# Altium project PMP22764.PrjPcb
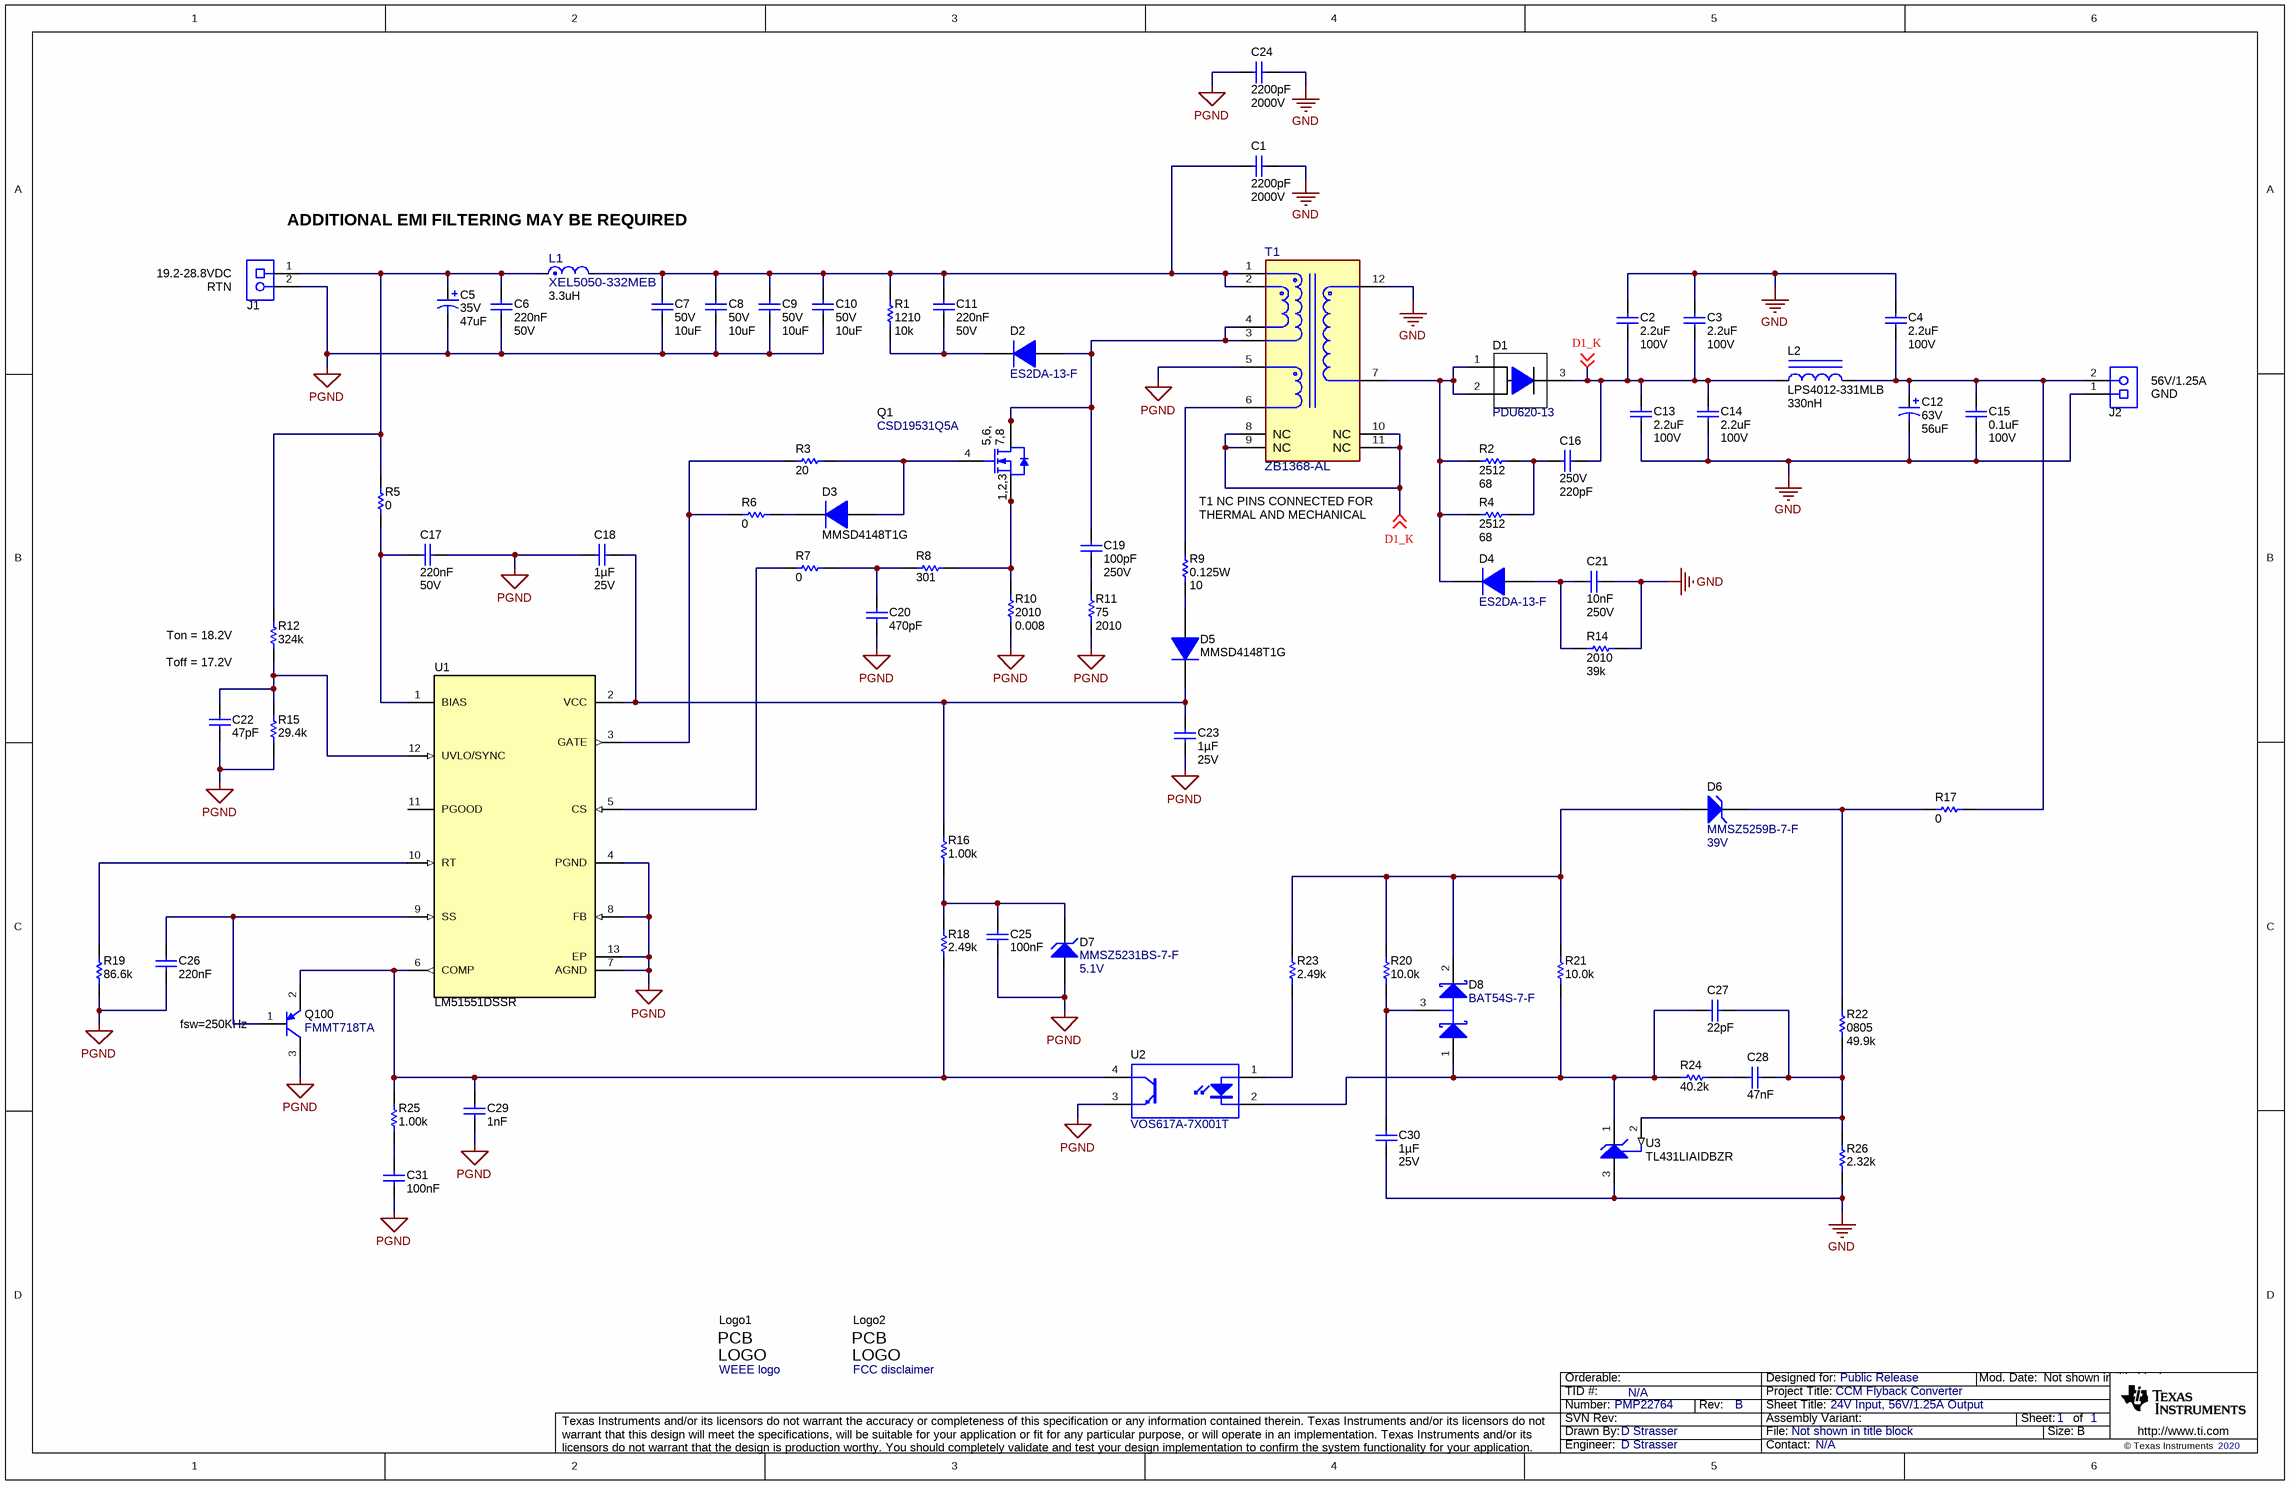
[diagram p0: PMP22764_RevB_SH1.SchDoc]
CopyrightYear: 2020; PCB_Layout: D Strasser; PCB_Rev: B; PRJ_Customer: Public Release; PRJ_Engineer: D Strasser; PRJ_Number: PMP22764; PRJ_Title: CCM Flyback Converter; SCH_Rev: B; TechSupport: N/A; TID: N/A
1 sheet, 76 parts. Net scope: global (net labels, ports and power ports of the same name join across sheets).
Board file: PMP22764_RevB.PcbDoc

## Sheet PMP22764_RevB_SH1.SchDoc: 24V Input, 56V/1.25A Output
size 431 x 279 mm; Date: Not shown in title block; ApprovedBy: Not shown in title block; CheckedBy: Not shown in title block; Author: Not shown in title block; CompanyName: Not shown in title block; DrawnBy: D Strasser; Engineer: Not shown in title block; Organization: Not shown in title block; Address1: Not shown in title block; Address2: Not shown in title block; Address3: Not shown in title block; Address4: Not shown in title block; DocumentNumber: 1; Revision: Use project parameter SCH_Rev; SheetNumber: 1; SheetTotal: 1; PageSetup: Record=PageOptions¦CenterHorizontal=True¦CenterVertical=True¦PrintScale=1.00¦XCorrection=1.00¦YCorrection=1.00¦PrintKind=0¦BorderSize=5000000¦LeftOffset=0¦BottomOffset=0¦Orientation=2¦PaperLength=1000¦PaperWidth=1000¦Scale=100¦PaperSource=15¦PrintQuality=600¦MediaType=1¦DitherType=10¦PaperKind=Letter¦PrintScaleMode=1

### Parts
C1  ValueDisplayed: 2200pF  Value2: 2000V  [1812_HV]  (hidden comment: Capacitor)
C2  ValueDisplayed: 2.2uF  Value2: 100V  [1210_270]  (hidden comment: Capacitor)
C3  ValueDisplayed: 2.2uF  Value2: 100V  [1210_270]  (hidden comment: Capacitor)
C4  ValueDisplayed: 2.2uF  Value2: 100V  [1210_270]  (hidden comment: Capacitor)
C5  VDC_V: 35V  ValueDisplayed: 47uF  [SM_RADIAL_6.3AMM]  (hidden comment: EEHZC1V470P)
C6  Cap_F: 220nF  VDC_V: 50V  [0805_HV]  (hidden comment: UMK212B7224KG-T)
C7  VDC_V: 50V  ValueDisplayed: 10uF  [1210_280]  (hidden comment: UMK325AB7106KM-T)
C8  VDC_V: 50V  ValueDisplayed: 10uF  [1210_280]  (hidden comment: UMK325AB7106KM-T)
C9  VDC_V: 50V  ValueDisplayed: 10uF  [1210_280]  (hidden comment: UMK325AB7106KM-T)
C10  VDC_V: 50V  ValueDisplayed: 10uF  [1210_280]  (hidden comment: UMK325AB7106KM-T)
C11  Cap_F: 220nF  VDC_V: 50V  [0805_HV]  (hidden comment: UMK212B7224KG-T)
C12  VDC_V: 63V  ValueDisplayed: 56uF  [SM_RADIAL_10BMM]  (hidden comment: EEHZC1J560P)
C13  ValueDisplayed: 2.2uF  Value2: 100V  [1210_270]  (hidden comment: Capacitor)
C14  ValueDisplayed: 2.2uF  Value2: 100V  [1210_270]  (hidden comment: Capacitor)
C15  ValueDisplayed: 0.1uF  Value2: 100V  [0805_HV]  (hidden comment: Capacitor)
C16  VDC_V: 250V  ValueDisplayed: 220pF  [0603]  (hidden comment: C1608C0G2E221J080AA)
C17  Cap_F: 220nF  VDC_V: 50V  [0805_HV]  (hidden comment: UMK212B7224KG-T)
C18  Cap_F: 1µF  VDC_V: 25V  [0805_HV]  (hidden comment: TMK212B7105KG-T)
C19  ValueDisplayed: 100pF  Value2: 250V  [0805_HV]  (hidden comment: Capacitor)
C20  Cap_F: 470pF  [0603L]  (hidden comment: 885012206081)
C21  Cap_F: 10nF  VDC_V: 250V  [0805_HV]  (hidden comment: QMK212B7103KG-T)
C22  ValueDisplayed: 47pF  [0603L]  (hidden comment: GRM1885C1H470JA01D)
C23  Cap_F: 1µF  VDC_V: 25V  [0805_HV]  (hidden comment: TMK212B7105KG-T)
C24  ValueDisplayed: 2200pF  Value2: 2000V  [1812_HV]  (hidden comment: Capacitor)
C25  Cap_F: 100nF  [0603L]  (hidden comment: 885012206071)
C26  Cap_F: 220nF  [0603L]  (hidden comment: C1608X7R1E224K080AC)
C27  ValueDisplayed: 22pF  [0603L]  (hidden comment: C0603C220J5GACTU)
C28  Cap_F: 47nF  [0603L]  (hidden comment: GRM188R71E473KA01D)
C29  Cap_F: 1nF  [0603L]  (hidden comment: 885012206083)
C30  Cap_F: 1µF  VDC_V: 25V  [0805_HV]  (hidden comment: TMK212B7105KG-T)
C31  Cap_F: 100nF  [0603L]  (hidden comment: 885012206071)
D1  PDU620-13  [POWERDI5]
D2  ES2DA-13-F  [SMA]
D3  MMSD4148T1G  [SOD-123]
D4  ES2DA-13-F  [SMA]
D5  MMSD4148T1G  [SOD-123]
D6  MMSZ5259B-7-F  value 39V  [SOD-123]
D7  MMSZ5231BS-7-F  value 5.1V  [SOD-323]
D8  BAT54S-7-F  [SOT-23]
J1  ED555/2DS  [TERM_BLK_ED555-2DS]  (value not drawn)
J2  Receptacle_2x1  [TERM_BLK_ED555-2DS]  (value not drawn)
L1  XEL5050-332MEB  value 3.3uH  [FP-XEL5050-332MEB_SMT_IND_5MM48_5MM28-MFG]
L2  ValueDisplayed: 330nH  [LPS4012]  (hidden comment: LPS4012-331MLB)
Logo1  WEEE logo  [WEEE_Minimum]  (no BOM)
Logo2  FCC disclaimer  [FCC_disclaimer]  (no BOM)
Q1  CSD19531Q5A  [DQJ0008A]
Q100  FMMT718TA  [SOT-23L]
R1  PackageReference: 1210  ValueDisplayed: 10k  [1210L]  (hidden comment: RC1210JR-0710KL)
R2  ValueDisplayed: 68  [2512]  (hidden comment: CRCW251268R0JNEG)
R3  ValueDisplayed: 20  [0603L]  (hidden comment: CRCW060320R0JNEA)
R4  ValueDisplayed: 68  [2512]  (hidden comment: CRCW251268R0JNEG)
R5  ValueDisplayed: 0  [0603L]  (hidden comment: Resistor)
R6  ValueDisplayed: 0  [0603L]  (hidden comment: Resistor)
R7  ValueDisplayed: 0  [0603L]  (hidden comment: Resistor)
R8  ValueDisplayed: 301  [0603L]  (hidden comment: CRCW0603301RFKEA)
R9  Value2: 0.125W  ValueDisplayed: 10  [0805_HV]  (hidden comment: CRCW080510R0JNEA)
R10  ValueDisplayed: 0.008  [2010]  (hidden comment: PMR50HZPFU8L00)
R11  ValueDisplayed: 75  PackageReference: 2010  [2010L]  (hidden comment: Resistor)
R12  ValueDisplayed: 324k  [0603L]  (hidden comment: CRCW0603324KFKEA)
R14  ValueDisplayed: 39k  [2010]  (hidden comment: CRCW201039K0JNEF)
R15  ValueDisplayed: 29.4k  [0603L]  (hidden comment: CRCW060329K4FKEA)
R16  ValueDisplayed: 1.00k  [0603L]  (hidden comment: CRCW06031K00FKEA)
R17  ValueDisplayed: 0  [0603L]  (hidden comment: Resistor)
R18  ValueDisplayed: 2.49k  [0603L]  (hidden comment: CRCW06032K49FKEA)
R19  ValueDisplayed: 86.6k  [0603L]  (hidden comment: CRCW060386K6FKEA)
R20  ValueDisplayed: 10.0k  [0603L]  (hidden comment: CRCW060310K0FKEA)
R21  ValueDisplayed: 10.0k  [0603L]  (hidden comment: CRCW060310K0FKEA)
R22  PackageReference: 0805  ValueDisplayed: 49.9k  [0805_HV]  (hidden comment: CRCW080549K9FKEA)
R23  ValueDisplayed: 2.49k  [0603L]  (hidden comment: CRCW06032K49FKEA)
R24  ValueDisplayed: 40.2k  [0603L]  (hidden comment: CRCW060340K2FKEA)
R25  ValueDisplayed: 1.00k  [0603L]  (hidden comment: CRCW06031K00FKEA)
R26  ValueDisplayed: 2.32k  [0603L]  (hidden comment: CRCW06032K32FKEA)
T1  ZB1368-AL  [FP-ZB1368-AL_PTH_XFRMR_33MM02_26MM75-MFG]
U1  LM51551DSSR  [DSS0012B]
U2  VOS617A-7X001T  [SSOP-4_VISHAY]
U3  TL431LIAIDBZR  [DBZ0003A_N]

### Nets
GND: C1.1 C2.1 C3.1 C4.1 C12.2(-) C13.2 C14.2 C15.1 C21.2 C24.1 C30.1 J2.1 R14.2 R26.2 T1.12 U3.3(ANODE)
PGND: C5.2(-) C6.2 C7.2 C8.2 C9.2 C10.2 C17.1 C18.2 C20.1 C22.1 C23.1 C24.2 C25.2 C26.2 C29.1 C31.2 D7.2(A) J1.2 Q100.3(C) R10.2 R11.1 R15.2 R19.2 T1.5 U1.4(PGND) U1.7(AGND) U1.8(FB) U1.13(EP) U2.3(E)
D1_K: C2.2 C3.2 C13.1 C14.1 C16.1 D1.3(K) L2.1 T1.8(NC) T1.9(NC) T1.10(NC) T1.11(NC) ; off-sheet D1_K
NetC1_2: C1.2 C7.1 C8.1 C9.1 C10.1 C11.1 L1.2 R1.1 T1.1 T1.2
NetC4_2: C4.2 C12.1(+) C15.2 J2.2 L2.2 R17.1
NetC5_1: C5.1(+) C6.1 J1.1 L1.1 R5.2 R12.1
NetC11_2: C11.2 D2.1(K) R1.2
NetC16_2: C16.2 R2.2 R4.2
NetC17_2: C17.2 R5.1 U1.1(BIAS)
NetC18_1: C18.1 C23.2 D5.1(K) R16.2 U1.2(VCC)
NetC19_1: C19.1 D2.2(A) Q1.5(D) Q1.6(D) Q1.7(D) Q1.8(D) Q1.9(D) T1.3 T1.4
NetC19_2: C19.2 R11.2
NetC20_2: C20.2 R7.2 R8.1
NetC21_1: C21.1 D4.2(A) R14.1
NetC22_2: C22.2 R12.2 R15.1 U1.12(UVLO/SYNC)
NetC25_1: C25.1 D7.1(K) R16.1 R18.1
NetC26_1: C26.1 Q100.1(B) U1.9(SS)
NetC27_1: C27.1 C28.1 R22.2 R26.1 U3.2(REF)
NetC27_2: C27.2 D8.1(A) R21.2 R24.1 U2.2(K) U3.1(CATHODE)
NetC28_2: C28.2 R24.2
NetC29_2: C29.2 Q100.2(E) R18.2 R25.2 U1.6(COMP) U2.4(C)
NetC30_2: C30.2 D8.3(C) R20.2
NetC31_1: C31.1 R25.1
NetD1_1: D1.1(A) D1.2(A) D4.1(K) R2.1 R4.1 T1.7
NetD3_1: D3.1(K) R6.2
NetD3_2: D3.2(A) Q1.4(G) R3.2
NetD5_2: D5.2(A) R9.2
NetD6_1: D6.1(K) R17.2 R22.1
NetD6_2: D6.2(A) D8.2(K) R20.1 R21.1 R23.1
NetQ1_1: Q1.1(S) Q1.2(S) Q1.3(S) R8.2 R10.1
NetR3_1: R3.1 R6.1 U1.3(GATE)
NetR7_1: R7.1 U1.5(CS)
NetR9_1: R9.1 T1.6
NetR19_1: R19.1 U1.10(RT)
NetR23_2: R23.2 U2.1(A)

Not connected (* = marked no-connect by the designer): U1 11(PGOOD)

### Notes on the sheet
- ADDITIONAL EMI FILTERING MAY BE REQUIRED
- (near J1) 19.2-28.8VDC
- (near J1) RTN
- (near J2) GND
- (near J2) 56V/1.25A
- T1 NC PINS CONNECTED FOR
- (near R9) THERMAL AND MECHANICAL
- (near R12) Ton = 18.2V
- Toff = 17.2V
- fsw=250KHz

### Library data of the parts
C1 C24 = CMP-0009358-2: CAP, CERM, 2200 pF, 2000 V, +/- 10%, X7R, 1812; PartNumber: C4532X7R3D222K130KA; Manufacturer: TDK; Polarized: N; Value: 2200pF; U/M: EA; Cap_F: 2.2nF; Value1: Unknown; VDC_V: 2kV; TaMin_C: -55°C; TaMax_C: 125°C; Cap_Case: 1812; SizeArea_mm2: 14.4; SizeAreaWB_mm2: 23.1; SizeX_mm: 4.5; SizeY_mm: 3.2; SizeZ_mm: 1.35; AEC Category: Q200
C2-C4 C13 C14 = CMP-0009232-2: CAP, CERM, 2.2 uF, 100 V, +/- 10%, X7R, 1210; PartNumber: GRM32ER72A225KA35L; Manufacturer: MuRata; Polarized: N; Value: 2.2uF; U/M: EA; Cap_F: 2.2µF; ESR_ohm: 7m; Value1: 0.007 ohm; IRMS_A: 4.4A; TaMin_C: -55°C; TaMax_C: 125°C; Cap_Case: 1210; SizeArea_mm2: 8; SizeAreaWB_mm2: 14.7; SizeX_mm: 3.2; SizeY_mm: 2.5; SizeZ_mm: 2.7; AEC Category: Q200
C5 = CMP-0012607-3: CAP, Polymer Hybrid, 47 uF, 35 V, +/- 20%, 60 ohm, 6.3x5.8 SMD; Manufacturer: Panasonic; TaMin_C: -55°C; ESR_ohm: 60; Polarized: Y; SizeAreaWB_mm2: 79.98; Value1: 60 ohm; Value: 47uF; TaMax_C: 125°C; SizeZ_mm: 6; SizeX_mm: 7.3; SizeY_mm: 6.6; SizeArea_mm2: 48.18; CompType: Capacitor; Cap_F: 47µF; IRMS_A: 900mA; AEC Category: Q200
C6 C11 C17 = CMP-0008422-2: CAP, CERM, 0.22 uF, 50 V, +/- 10%, X7R, 0805; Manufacturer: Taiyo Yuden; TaMin_C: -55°C; Polarized: N; SizeAreaWB_mm2: 6.75; Value1: Unknown; U/M: EA; Value: 0.22uF; TaMax_C: 125°C; SizeZ_mm: 1.45; SizeX_mm: 2; SizeY_mm: 1.25; Cap_Case: 0805; SizeArea_mm2: 2.5; AEC Category: Q200
C7-C10 = CMP-0009259-2: CAP, CERM, 10 uF, 50 V, +/- 10%, X7R, 1210; Manufacturer: Taiyo Yuden; TaMin_C: -55°C; Polarized: N; SizeAreaWB_mm2: 14.7; Value1: Unknown; U/M: EA; Value: 10uF; TaMax_C: 125°C; SizeZ_mm: 2.8; SizeX_mm: 3.2; SizeY_mm: 2.5; Cap_Case: 1210; SizeArea_mm2: 8; Cap_F: 10µF; AEC Category: Q200
C12 = CMP-0012603-3: CAP, Polymer Hybrid, 56 uF, 63 V, +/- 20%, 30 ohm, 10x10 SMD; Manufacturer: Panasonic; TaMin_C: -55°C; ESR_ohm: 30; Polarized: Y; SizeAreaWB_mm2: 159.9; Value1: 30 ohm; Value: 56uF; TaMax_C: 125°C; SizeZ_mm: 10.2; SizeX_mm: 11; SizeY_mm: 10.3; SizeArea_mm2: 113.3; CompType: Capacitor; Cap_F: 56µF; IRMS_A: 1.4A; AEC Category: Q200
C15 = CMP-0007886-2: CAP, CERM, 0.1 uF, 100 V, +/- 10%, X7R, 0805; PartNumber: C2012X7R2A104K125AA; Manufacturer: TDK; Polarized: N; Value: 0.1uF; U/M: EA; Cap_F: 100nF; ESR_ohm: 0.020726; Value1: 0.020726 ohm; IRMS_A: 1.456A; TaMin_C: -55°C; TaMax_C: 125°C; Cap_Case: 0805; SizeArea_mm2: 2.5; SizeAreaWB_mm2: 6.75; SizeX_mm: 2; SizeY_mm: 1.25; SizeZ_mm: 1.45; AEC Category: Q200
C16 = CMP-0006996-4: CAP, CERM, 220 pF, 250 V, +/- 5%, C0G/NP0, 0603; Manufacturer: TDK; TaMin_C: -55°C; Polarized: N; SizeAreaWB_mm2: 4.68; Value1: Unknown; U/M: EA; Value: 220pF; TaMax_C: 125°C; SizeZ_mm: 1; SizeX_mm: 1.6; SizeY_mm: 0.8; SizeArea_mm2: 1.28; AEC Category: Q200
C18 C23 C30 = CMP-0008412-2: CAP, CERM, 1 uF, 25 V, +/- 10%, X7R, 0805; Manufacturer: Taiyo Yuden; TaMin_C: -55°C; Polarized: N; SizeAreaWB_mm2: 6.75; Value1: Unknown; U/M: EA; Value: 1uF; TaMax_C: 125°C; SizeZ_mm: 1.45; SizeX_mm: 2; SizeY_mm: 1.25; Cap_Case: 0805; SizeArea_mm2: 2.5; AEC Category: Q200
C19 = CMP-0008236-2: CAP, CERM, 100 pF, 250 V, +/- 5%, C0G/NP0, 0805; PartNumber: GRM21A5C2E101JW01D; Manufacturer: MuRata; Polarized: N; Value: 100pF; U/M: EA; Value1: Unknown; TaMin_C: -55°C; TaMax_C: 125°C; Cap_Case: 0805; SizeArea_mm2: 2.5; SizeAreaWB_mm2: 6.75; SizeX_mm: 2; SizeY_mm: 1.25; SizeZ_mm: 1.45; AEC Category: Q200
C20 = CMP-0006834-5: CAP, CERM, 470 pF, 50 V, +/- 10%, X7R, 0603; Manufacturer: Wurth Elektronik; TaMin_C: -55°C; Polarized: N; SizeAreaWB_mm2: 4.68; Value1: Unknown; U/M: EA; Value: 470pF; TaMax_C: 125°C; SizeZ_mm: 1; SizeX_mm: 1.6; SizeY_mm: 0.8; Cap_Case: 0603; Value2: 50V; SizeArea_mm2: 1.28; AEC Category: Q200
C21 = CMP-0008408-2: CAP, CERM, 0.01 uF, 250 V, +/- 10%, X7R, 0805; Manufacturer: Taiyo Yuden; TaMin_C: -55°C; Polarized: N; SizeAreaWB_mm2: 6.75; Value1: Unknown; U/M: EA; Value: 0.01uF; TaMax_C: 125°C; SizeZ_mm: 1.45; SizeX_mm: 2; SizeY_mm: 1.25; Cap_Case: 0805; SizeArea_mm2: 2.5; AEC Category: Q200
C22 = CMP-0007220-4: CAP, CERM, 47 pF, 50 V, +/- 5%, C0G/NP0, 0603; Manufacturer: MuRata; TaMin_C: -55°C; Polarized: N; SizeAreaWB_mm2: 4.68; Value1: Unknown; U/M: EA; Value: 47pF; TaMax_C: 125°C; SizeZ_mm: 1; SizeX_mm: 1.6; SizeY_mm: 0.8; Cap_Case: 0603; Value2: 50V; SizeArea_mm2: 1.28; AEC Category: Q200
C25 C31 = CMP-0006832-5: CAP, CERM, 0.1 uF, 25 V, +/- 10%, X7R, 0603; Manufacturer: Wurth Elektronik; TaMin_C: -55°C; Polarized: N; SizeAreaWB_mm2: 4.68; Value1: Unknown; U/M: EA; Value: 0.1uF; TaMax_C: 125°C; SizeZ_mm: 1; SizeX_mm: 1.6; SizeY_mm: 0.8; Cap_Case: 0603; Value2: 25V; SizeArea_mm2: 1.28; AEC Category: Q200
C26 = CMP-0007042-4: CAP, CERM, 0.22 uF, 25 V, +/- 10%, X7R, 0603; Manufacturer: TDK; TaMin_C: -55°C; Polarized: N; SizeAreaWB_mm2: 4.68; Value1: Unknown; U/M: EA; Value: 0.22uF; TaMax_C: 125°C; SizeZ_mm: 1; SizeX_mm: 1.6; SizeY_mm: 0.8; Cap_Case: 0603; Value2: 25V; SizeArea_mm2: 1.28; AEC Category: Q200
C27 = CMP-0006892-4: CAP, CERM, 22 pF, 50 V, +/- 5%, C0G/NP0, 0603; Manufacturer: Kemet; TaMin_C: -55°C; Polarized: N; SizeAreaWB_mm2: 4.68; Value1: Unknown; U/M: EA; Value: 22pF; TaMax_C: 125°C; SizeZ_mm: 1; SizeX_mm: 1.6; SizeY_mm: 0.8; Cap_Case: 0603; Value2: 50V; SizeArea_mm2: 1.28; AEC Category: Q200
C28 = CMP-0007423-4: CAP, CERM, 0.047 uF, 25 V, +/- 10%, X7R, 0603; Manufacturer: MuRata; TaMin_C: -55°C; Polarized: N; SizeAreaWB_mm2: 4.68; Value1: Unknown; U/M: EA; TaMax_C: 125°C; SizeZ_mm: 1; SizeX_mm: 1.6; SizeY_mm: 0.8; Cap_Case: 0603; Value2: 25V; SizeArea_mm2: 1.28; AEC Category: Q200
C29 = CMP-0064933-4: CAP, CERM, 1000 pF, 50 V,+/- 10%, X7R, 0603; Manufacturer: Wurth Elektronik; TaMin_C: -55°C; Polarized: N; SizeAreaWB_mm2: 4.68; Value1: Unknown; U/M: EA; Value: 1000pF; TaMax_C: 125°C; SizeZ_mm: 1; SizeX_mm: 1.6; SizeY_mm: 0.8; Cap_Case: 0603; Value2: 50V; SizeArea_mm2: 1.28; AEC Category: Q200
D1 = CMP-0077019-2: Diode, Ultrafast, 200 V, 6 A, PowerDI5; Manufacturer: Diodes Inc.; SizeY_mm: 3.9; Value1: 6A; SizeArea_mm2: 24.96; SizeZ_mm: 1.05; Vf_V: 940mV; SizeX_mm: 6.4; Value2: 0.94V; Value: 200V; SizeAreaWB_mm2: 49.56; TJmax_C: 175°C; AEC Category: Q101; Green_Lifecycle: Not Set; Green_REACh: Incomplete
D2 D4 = CMP-0076892-2: Diode, Superfast Rectifier, 200 V, 2 A, SMA; Manufacturer: Diodes Inc.; Vf_V: 920mV; SizeY_mm: 2.92; RJC_CperW: 20.0; Value: 200V; SizeX_mm: 5.59; Value1: 2A; Value2: 0.92V; AEC Category: Q101; SizeAreaWB_mm2: 37.3428; Green_REACh: Incomplete; SizeArea_mm2: 16.3228; SizeZ_mm: 2.87; Green_Lifecycle: Not Set; TJmax_C: 150°C
D3 D5 = CMP-0029032-2: Diode, Switching, 100 V, 0.2 A, SOD-123; Manufacturer: ON Semiconductor; Vf_V: 1V; Value: 100V; Value1: 0.2A; Io_A: 200mA; TJmax_C: 150°C; SizeAreaWB_mm2: 13.095; SizeArea_mm2: 6.545; SizeX_mm: 3.85; SizeY_mm: 1.7; SizeZ_mm: 1.35; AEC Category: Q101; Green_Lifecycle: Active; Green_REACh: Passed
D6 = CMP-0005764-4: Diode, Zener, 39 V, 500 mW, SOD-123; Manufacturer: Diodes Inc.; SizeZ_mm: 1.35; AEC Category: Q101; RJA_CperW: 350; Value1: 0.5W; SizeX_mm: 3.85; SizeY_mm: 1.7; Power_W: 500mW; SizeArea_mm2: 6.545; SizeAreaWB_mm2: 13.095
D7 = CMP-0005854-3: Diode, Zener, 5.1 V, 200 mW, SOD-323; Manufacturer: Diodes Inc.; SizeX_mm: 2.7; SizeZ_mm: 1; RJA_CperW: 350; Power_W: 200mW; SizeAreaWB_mm2: 8.695; AEC Category: Q101; Value1: 0.2W; SizeArea_mm2: 3.645; SizeY_mm: 1.35
D8 = CMP-0028456-2: Diode, Schottky, 30 V, 0.2 A, SOT-23; Manufacturer: Diodes Inc.; Vf_V: 650mV; SizeAreaWB_mm2: 14; SizeX_mm: 2.5; TJmax_C: 125°C; SizeZ_mm: 1.1; Value2: 0.65V; SizeArea_mm2: 7.5; SizeY_mm: 3; Vr_V: 30V; AEC Category: Q101; Io_A: 200mA; Value1: 0.2A; Green_Lifecycle: Active; Value: 30V; Green_REACh: Passed
J1 = CMP-0074913-1: Terminal Block, 3.5mm Pitch, 2x1, TH; Manufacturer: On-Shore Technology; Cert_VDE: Y; CNHeader: False; Current_A: 6A; Green_Lifecycle: Active; Shrouded: N; Gender: Female; Green_REACh: Passed; Voltage_V: 150V; Row_Count: 1; Pitch_mm: 3.5; ContactFinish: Brass; CT: True
J2 = CMP-0074913-1: Terminal Block, 3.5mm Pitch, 2x1, TH; PartNumber: ED555/2DS; Manufacturer: On-Shore Technology; Pitch_mm: 3.5; Gender: Female; Shrouded: N; Row_Count: 1; ContactFinish: Brass; Current_A: 6A; Voltage_V: 150V; Cert_CULUS: Y; CNHeader: False; CT: True; Green_Lifecycle: Active; Green_REACh: Passed
L1 = CMP-0090124-1: Shielded Power Inductor, 3.3uH, ±20%, 7.8A, 14.6mΩ max; Manufacturer: Coilcraft; AEC Qualified: Yes; Test Frequency: 1MHz; Self Resonant Frequency: 31MHz; Ind_H: 3.3µH; Isat: 8.4A; TaMin_C: -40°C; TaMax_C: +125°C; Standoff Height: 0.2mm; DCR_ohm: 0.0146; Shrouded: true; Material: Composite; SizeZ_mm: 5.1mm; AEC Grade: Grade 1
L2 = CMP-0060464-1: Inductor, Shielded Drum Core, Ferrite, 330 nH, 3 A, 0.03 ohm, SMD; Manufacturer: Coilcraft; Isat: 5.5A @ 30% inductance drop; Irms: 3A @ 40C rise; Green_Lifecycle: Not Set; SizeAreaWB_mm2: 25; DCR_ohm: 0.03; Green_REACh: Incomplete; Value: 330nH; Imax_A: 3A; SizeZ_mm: 1.2; SizeX_mm: 4; SizeArea_mm2: 16; AEC Category: Q200
Logo1 = CMP-0074769-1
Logo2 = CMP-0074847-1: FCC_disclaimer
Q1 = CMP-0000956-2: MOSFET, N-CH, 100 V, 16 A, DQJ0008A (VSONP-8); Alternate Manufacturer: None; Manufacturer: Texas Instruments; SizeZ_mm: 1.1; ChType: N; Value2: 36 nC; VdsMax_V: 100V; SizeX_mm: 6; SizeY_mm: 4.9; Vgs_V: 20V; QgTyp_nC: 36; Value: 100V; SizeArea_mm2: 29.4; AEC Category: Q101; IdsMax_A: 16A; SizeAreaWB_mm2: 55.2; U/M: EA
Q100 = CMP-0000330-2: Transistor, PNP, 20 V, 1.5 A, SOT-23; Manufacturer: Diodes Inc.; TaMax_C: 150°C; Value2: 6; Value1: 1.5 A; Vcesat1_V: 20V; SizeX_mm: 2.5; SizeY_mm: 3; TaMin_C: -55°C; IcRated_A: 1.5A; CompType: BJT; SizeZ_mm: 1.1; Value: 20 V; SizeArea_mm2: 7.5; NPN: 0; PNP: 1; AEC Category: Q101; SizeAreaWB_mm2: 14; U/M: EA
R1 = CMP-0083442-1: RES, 10 k, 5%, 0.5 W, 1210; Manufacturer: Yageo; Power_W: 500mW; TempCo: 100 ppm/C; SizeAreaWB_mm2: 14.7; Value_Code: 10k0; Value: 10k; EIA_Code: E24; SizeX_mm: 3.2; SizeY_mm: 2.5; SizeZ_mm: 1.35; Value2: 0.5W; SizeArea_mm2: 8; AEC Qualified: N; VDC_V: 200V; AEC Category: Q200
R2 R4 = CMP-0015995-3: RES, 68, 5%, 1 W, AEC-Q200 Grade 0, 2512; Manufacturer: Vishay-Dale; Power_W: 1W; TempCo: 200 ppm/C; Value_Code: 68R0; Value: 68; EIA_Code: E24; SizeX_mm: 6.3; SizeY_mm: 3.2; SizeZ_mm: 0.71; SizeArea_mm2: 20.16; AEC Qualified: Y; VDC_V: 500V; AEC Grade: 0; AEC Category: Q200
R3 = CMP-0025754-4: RES, 20, 5%, 0.1 W, AEC-Q200 Grade 0, 0603; Manufacturer: Vishay-Dale; Power_W: 100mW; TempCo: 200 ppm/C; Value_Code: 20R0; Value: 20; EIA_Code: E24; SizeX_mm: 1.6; SizeY_mm: 0.8; SizeZ_mm: 1; Value2: 0.1W; SizeArea_mm2: 1.28; AEC Qualified: Y; VDC_V: 75V; AEC Category: Q200; AEC Grade: 0
R5-R7 R17 = CMP-0025697-4: RES, 0, 5%, 0.1 W, AEC-Q200 Grade 0, 0603; PartNumber: CRCW06030000Z0EA; Manufacturer: Vishay-Dale; Value: 0; Value_Code: 0000; Power_W: 100mW; Value2: 0.1W; VDC_V: 75V; TempCo: 200 ppm/C; SizeArea_mm2: 1.28; SizeX_mm: 1.6; SizeY_mm: 0.8; SizeZ_mm: 1; EIA_Code: E24; AEC Category: Q200; AEC Qualified: Y
R8 = CMP-0022321-5: RES, 301, 1%, 0.1 W, AEC-Q200 Grade 0, 0603; Manufacturer: Vishay-Dale; Power_W: 100mW; TempCo: 100 ppm/C; Value_Code: 301R; Value: 301; EIA_Code: E96; SizeX_mm: 1.6; SizeY_mm: 0.8; SizeZ_mm: 1; Value2: 0.1W; SizeArea_mm2: 1.28; AEC Qualified: Y; VDC_V: 75V; AEC Category: Q200; AEC Grade: 0
R9 = CMP-0020448-3: RES, 10, 5%, 0.125 W, AEC-Q200 Grade 0, 0805; Manufacturer: Vishay-Dale; Power_W: 125mW; TempCo: 200 ppm/C; Value_Code: 10R0; Value: 10; EIA_Code: E24; SizeX_mm: 2; SizeY_mm: 1.25; SizeZ_mm: 1.45; SizeArea_mm2: 2.5; AEC Qualified: Y; VDC_V: 150V; AEC Category: Q200; AEC Grade: 0
R10 = CMP-0016540-2: RES, 0.008, 1%, 1 W, 2010; Manufacturer: Rohm; Power_W: 1W; TempCo: 100 ppm/C; Value_Code: 8L000; U/M: EA; Value: 0.008; EIA_Code: E96; Res_ohm: 8m; SizeX_mm: 5; SizeY_mm: 2.5; SizeZ_mm: 1.66; SizeArea_mm2: 12.5; AEC Category: Q200
R11 = CMP-0016178-3: RES, 75, 5%, 0.75 W, AEC-Q200 Grade 0, 2010; PartNumber: CRCW201075R0JNEF; Manufacturer: Vishay-Dale; Value: 75; Value_Code: 75R0; Power_W: 750mW; Value2: 0.75W; VDC_V: 400V; TempCo: 200 ppm/C; SizeArea_mm2: 12.5; SizeX_mm: 5; SizeY_mm: 2.5; SizeZ_mm: 1.66; EIA_Code: E24; AEC Category: Q200; AEC Qualified: Y; AEC Grade: 0
R12 = CMP-0022332-4: RES, 324 k, 1%, 0.1 W, AEC-Q200 Grade 0, 0603; Manufacturer: Vishay-Dale; Power_W: 100mW; TempCo: 100 ppm/C; Value: 324k; EIA_Code: E96; SizeX_mm: 1.6; SizeY_mm: 0.8; SizeZ_mm: 1; Value2: 0.1W; SizeArea_mm2: 1.28; AEC Qualified: Y; VDC_V: 75V; AEC Category: Q200; AEC Grade: 0
R14 = CMP-0016129-3: RES, 39 k, 5%, 0.75 W, AEC-Q200 Grade 0, 2010; Manufacturer: Vishay-Dale; Power_W: 750mW; TempCo: 200 ppm/C; Value_Code: 39k0; Value: 39k; EIA_Code: E24; SizeX_mm: 5; SizeY_mm: 2.5; SizeZ_mm: 1.66; Value2: 0.75W; SizeArea_mm2: 12.5; AEC Qualified: Y; VDC_V: 400V; AEC Grade: 0; AEC Category: Q200
R15 = CMP-0022266-4: RES, 29.4 k, 1%, 0.1 W, AEC-Q200 Grade 0, 0603; Manufacturer: Vishay-Dale; Power_W: 100mW; TempCo: 100 ppm/C; Value_Code: 29k4; Value: 29.4k; EIA_Code: E96; SizeX_mm: 1.6; SizeY_mm: 0.8; SizeZ_mm: 1; Value2: 0.1W; SizeArea_mm2: 1.28; AEC Qualified: Y; VDC_V: 75V; AEC Category: Q200; AEC Grade: 0
R16 R25 = CMP-0022109-5: RES, 1.00 k, 1%, 0.1 W, AEC-Q200 Grade 0, 0603; Manufacturer: Vishay-Dale; CompType: Resistor; Value: 1.00k; Res_ohm: 1k; Value_Code: 1k00; Power_W: 100mW; Value2: 0.1W; VDC_V: 75V; TempCo: 100 ppm/C; SizeArea_mm2: 1.28; SizeX_mm: 1.6; SizeY_mm: 0.8; SizeZ_mm: 1; EIA_Code: E96; AEC Category: Q200; AEC Qualified: Y; AEC Grade: 0
R18 R23 = CMP-0022277-4: RES, 2.49 k, 1%, 0.1 W, AEC-Q200 Grade 0, 0603; Manufacturer: Vishay-Dale; Power_W: 100mW; TempCo: 100 ppm/C; Value_Code: 2k49; Value: 2.49k; EIA_Code: E96; SizeX_mm: 1.6; SizeY_mm: 0.8; SizeZ_mm: 1; Value2: 0.1W; SizeArea_mm2: 1.28; AEC Qualified: Y; VDC_V: 75V; AEC Category: Q200; AEC Grade: 0
R19 = CMP-0022628-4: RES, 86.6 k, 1%, 0.1 W, AEC-Q200 Grade 0, 0603; Manufacturer: Vishay-Dale; Power_W: 100mW; TempCo: 100 ppm/C; Value_Code: 86k6; Value: 86.6k; EIA_Code: E96; SizeY_mm: 0.8; SizeZ_mm: 1; Value2: 0.1W; SizeArea_mm2: 1.28; AEC Qualified: Y; VDC_V: 75V; AEC Category: Q200; SizeX_mm: 1.6; AEC Grade: 0
R20 R21 = CMP-0021998-4: RES, 10.0 k, 1%, 0.1 W, AEC-Q200 Grade 0, 0603; Manufacturer: Vishay-Dale; Power_W: 100mW; TempCo: 100 ppm/C; Value_Code: 10k0; Value: 10.0k; EIA_Code: E96; Res_ohm: 10k; SizeX_mm: 1.6; SizeY_mm: 0.8; SizeZ_mm: 1; Value2: 0.1W; SizeArea_mm2: 1.28; AEC Qualified: Y; VDC_V: 75V; AEC Category: Q200; AEC Grade: 0
R22 = CMP-0021283-3: RES, 49.9 k, 1%, 0.125 W, AEC-Q200 Grade 0, 0805; Manufacturer: Vishay-Dale; Power_W: 125mW; TempCo: 100 ppm/C; Value_Code: 49k9; Value: 49.9k; EIA_Code: E96; SizeX_mm: 2; SizeY_mm: 1.25; SizeZ_mm: 1.45; Value2: 0.125W; SizeArea_mm2: 2.5; AEC Qualified: Y; VDC_V: 150V; AEC Category: Q200; AEC Grade: 0
R24 = CMP-0022410-4: RES, 40.2 k, 1%, 0.1 W, AEC-Q200 Grade 0, 0603; Manufacturer: Vishay-Dale; Power_W: 100mW; TempCo: 100 ppm/C; Value_Code: 40k2; Value: 40.2k; EIA_Code: E96; SizeX_mm: 1.6; SizeY_mm: 0.8; SizeZ_mm: 1; Value2: 0.1W; SizeArea_mm2: 1.28; AEC Qualified: Y; VDC_V: 75V; AEC Category: Q200; AEC Grade: 0
R26 = CMP-0022274-4: RES, 2.32 k, 1%, 0.1 W, AEC-Q200 Grade 0, 0603; Manufacturer: Vishay-Dale; Power_W: 100mW; TempCo: 100 ppm/C; Value_Code: 2k32; Value: 2.32k; EIA_Code: E96; SizeX_mm: 1.6; SizeY_mm: 0.8; SizeZ_mm: 1; Value2: 0.1W; SizeArea_mm2: 1.28; AEC Qualified: Y; VDC_V: 75V; AEC Category: Q200; AEC Grade: 0
T1 = CMP-0091023-1: Flyback Transformer EFD25 12 Pins input:18-30Vin, output:56/1.25A, Aux:10.6V; Manufacturer: Coilcraft; Ns1toNp: 1:0.4:2; AEC Qualified: No; Ind_H: 12.75µH; Voltage_Isolation_Vrms: 2500Vrms; SizeZ_mm: 14mm
U1 = CMP-0085932-2: 2.2-MHz Wide Input Nonsynchronous Boost, Sepic, Flyback Controller, DSS0012B (WSON-12); Manufacturer: Texas Instruments; Alternate PartNumber: LM51551DSST; SizeAreaWB_mm2: 12; SizeArea_mm2: 6; AEC Category: Q200; CompType: IC; AEC Qualified: N; SizeX_mm: 2; SizeZ_mm: 0.8; SizeY_mm: 3
U2 = CMP-0006163-3: Optocoupler, 3.75 kV, 80-160% CTR, SMT; Manufacturer: Vishay-Semiconductor; CTR (Max): 160%; CTR (Min): 80%; Voltage_Isolation_Vrms: 3.75kV
U3 = CMP-0084729-1: Programmable Shunt Regulator with Optimized Reference Current, DBZ0003A (SOT-23-3); Manufacturer: Texas Instruments; SizeY_mm: 3; SizeZ_mm: 1.12; SizeX_mm: 2.5; SizeAreaWB_mm2: 14; CompType: IC; AEC Qualified: N; AEC Category: Q200; SizeArea_mm2: 7.5

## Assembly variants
001: not fitted C19 R11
